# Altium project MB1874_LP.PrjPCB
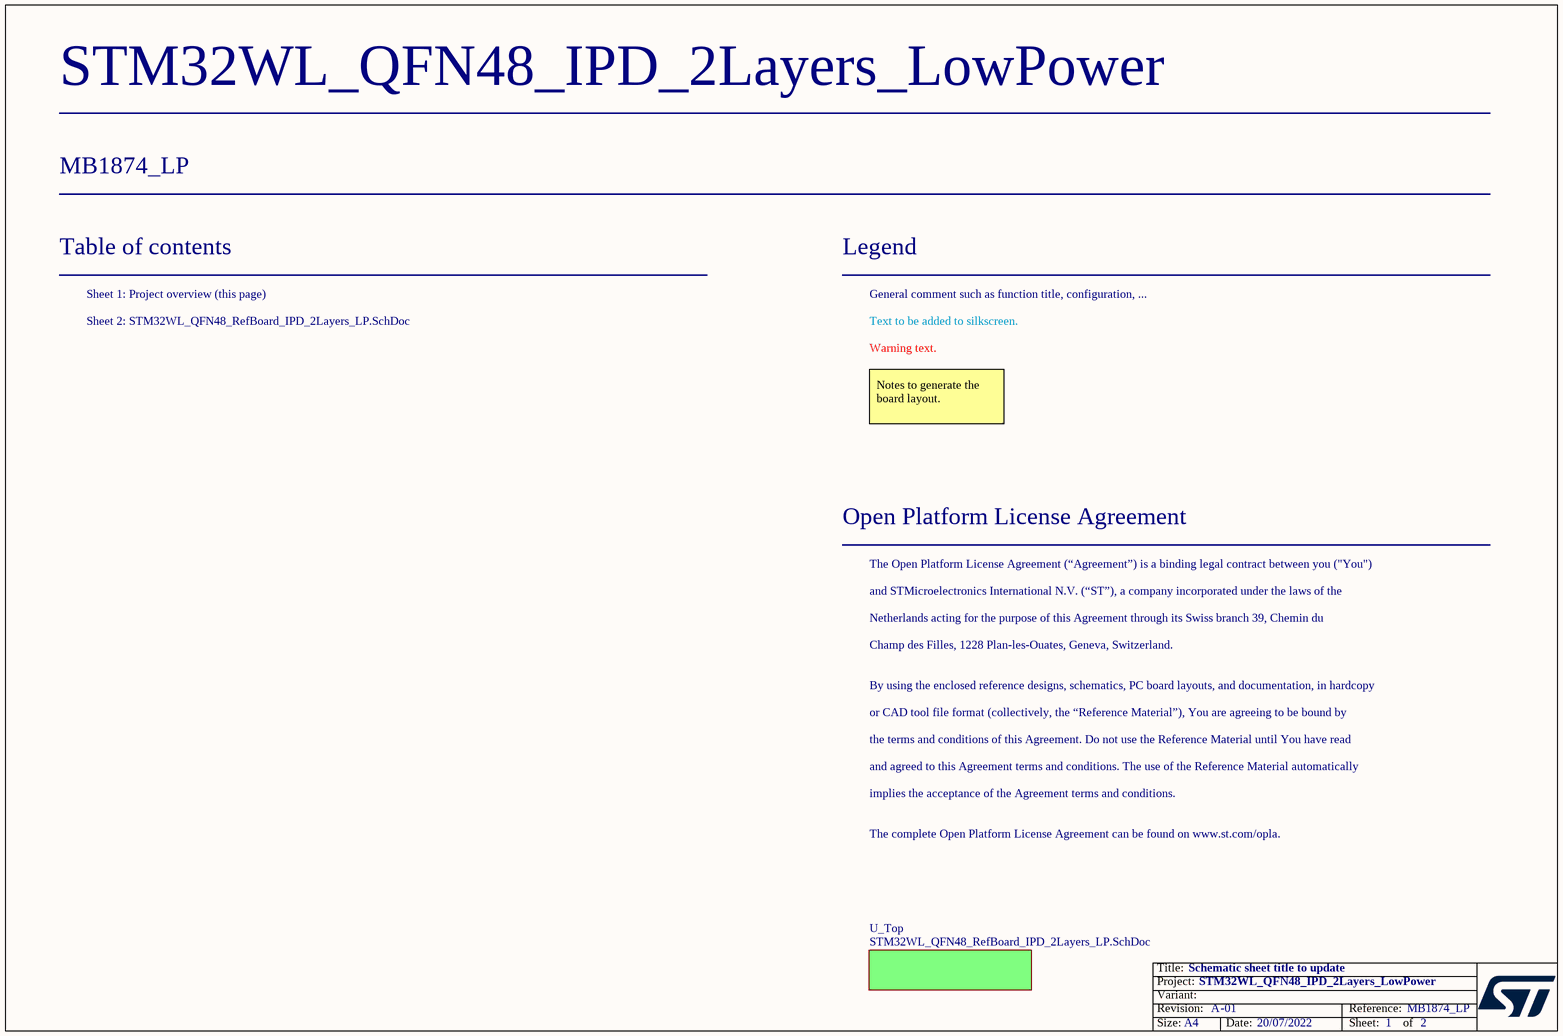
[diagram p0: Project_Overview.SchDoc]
Board_Assembly_Revision: 01; Board_Document_Date: 20/07/2022; Board_Name: STM32WL_QFN48_IPD_2Layers_LowPower; Board_PCB_Revision: A; Board_Reference: MB1874_LP
2 sheets, 73 parts. Net scope: flat (ports and power ports of the same name join across sheets).
Board file: MB1874_LP.PcbDoc
Sheets:
  Project_Overview.SchDoc
    U_Top = STM32WL_QFN48_RefBoard_IPD_2Layers_LP.SchDoc

## Sheet Project_Overview.SchDoc: Schematic sheet title to update
size A4; Date: Not used; ApprovedBy: Not used; CheckedBy: Not used; Author: Not used; CompanyName: STMicroelectronics; DrawnBy: Not used; Engineer: Not used; Organization: Not used; Address1: Not used; Address2: Not used; Address3: Not used; Address4: Not used; DocumentNumber: Not used; Revision: Not used; SheetNumber: 1; SheetTotal: 2

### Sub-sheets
U_Top = STM32WL_QFN48_RefBoard_IPD_2Layers_LP.SchDoc: no entries

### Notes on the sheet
- Table of contents
- Sheet 1: Project overview (this page)
- Legend
- General comment such as function title, configuration, ...
- Sheet 2: STM32WL_QFN48_RefBoard_IPD_2Layers_LP.SchDoc
- Text to be added to silkscreen.
- Warning text.
- Notes to generate the board layout.
- Open Platform License Agreement
- The Open Platform License Agreement (“Agreement”) is a binding legal contract between you ("You")
- and STMicroelectronics International N.V. (“ST”), a company incorporated under the laws of the
- Netherlands acting for the purpose of this Agreement through its Swiss branch 39, Chemin du
- Champ des Filles, 1228 Plan-les-Ouates, Geneva, Switzerland.
- By using the enclosed reference designs, schematics, PC board layouts, and documentation, in hardcopy
- or CAD tool file format (collectively, the “Reference Material”), You are agreeing to be bound by
- the terms and conditions of this Agreement. Do not use the Reference Material until You have read
- and agreed to this Agreement terms and conditions. The use of the Reference Material automatically
- implies the acceptance of the Agreement terms and conditions.
- The complete Open Platform License Agreement can be found on www.st.com/opla.

## Sheet STM32WL_QFN48_RefBoard_IPD_2Layers_LP.SchDoc: STM32WL UFQFPN48 REF BOARD - Direct Tie - HP- 2L
size A3; DocumentNumber: MBxxxx; Revision: A; SheetNumber: 2; SheetTotal: 2
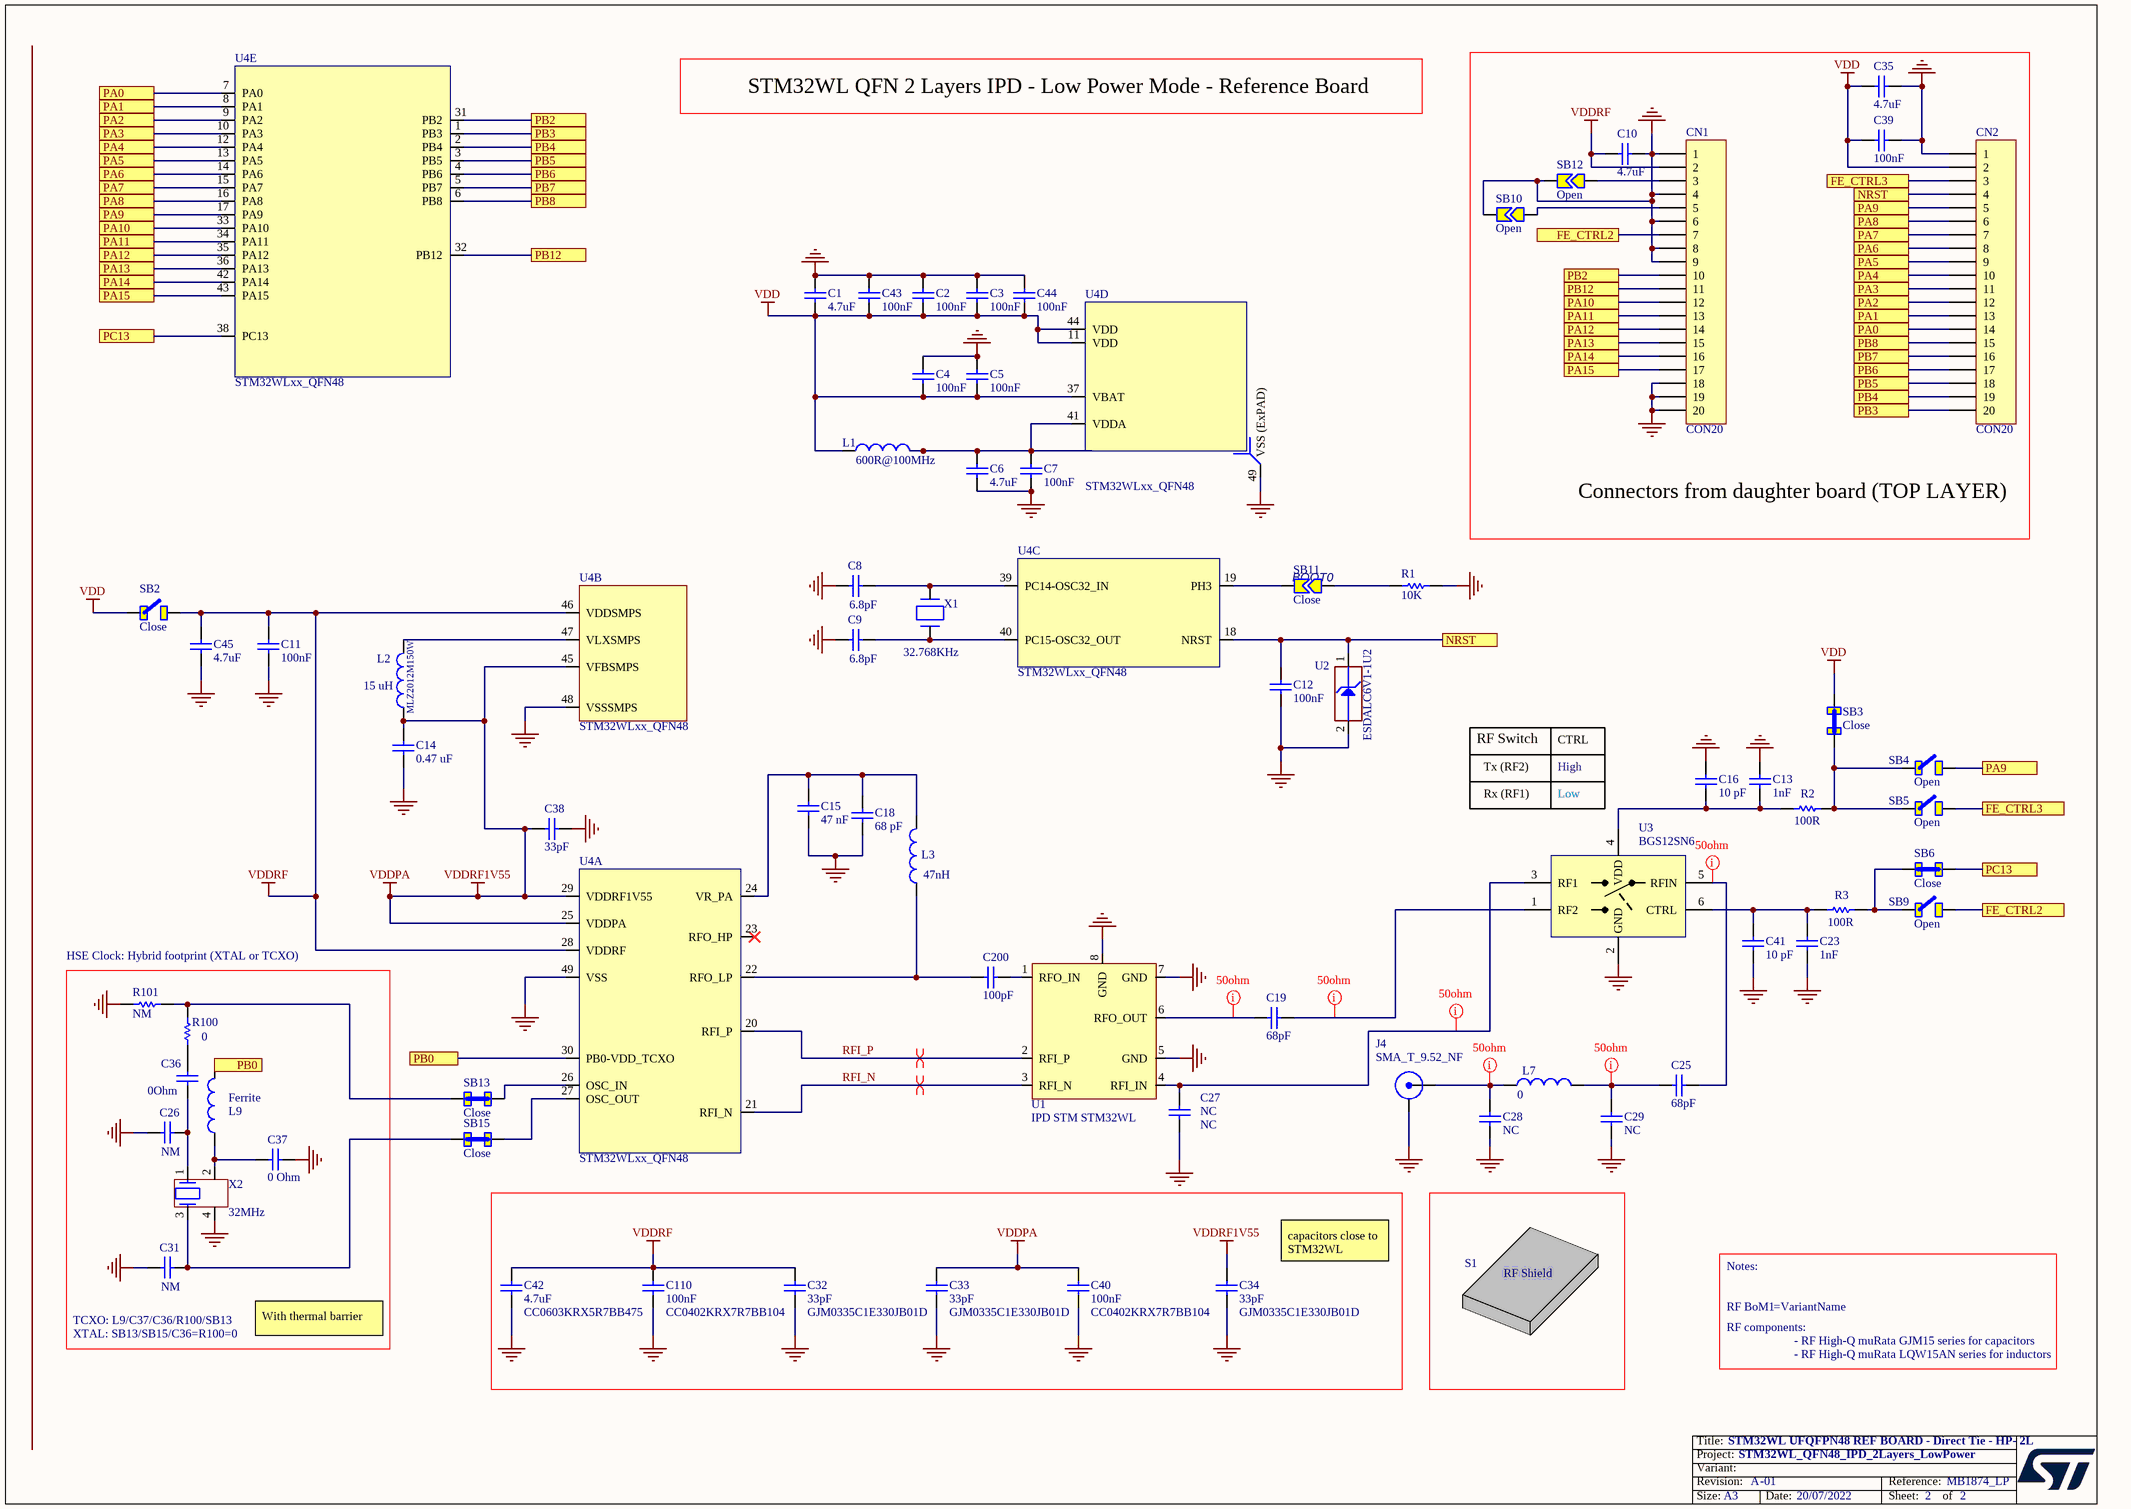
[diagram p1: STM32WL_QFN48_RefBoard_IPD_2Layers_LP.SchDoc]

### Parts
C1  value 4.7uF  [CAPC1608X09N]
C2  value 100nF  [CAPC1005X06N]
C3  value 100nF  [0201]
C4  value 100nF  [CAPC1005X06N]
C5  value 100nF  [0201]
C6  value 4.7uF  [CAPC1608X09N]
C7  value 100nF  [CAPC1005X06N]
C8  value 6.8pF  [0402]  (hidden comment: Capacitor)
C9  value 6.8pF  [0402]  (hidden comment: Capacitor)
C10  value 4.7uF  [CAPC1608X09N]
C11  value 100nF  [CAPC1005X06N]
C12  value 100nF  [0402]
C13  value 1nF  [CAPC1005X06N]
C14  value 0.47 uF  [CAPC1608X09N]
C15  value 47 nF  [0402]
C16  value 10 pF  [CAPC1005X06N]
C18  value 68 pF  [0402]
C19  value 68pF  [0402]
C23  value 1nF  [CAPC1005X06N]
C25  value 68pF  [0402_2]
C26  value NM  [0402]  (hidden comment: Capacitor)
C27  NC  [0402_2]
C28  value NC  [0402]  (hidden comment: MCD-00102)
C29  value NC  [0402]  (hidden comment: MCD-00102)
C31  value NM  [0402]  (hidden comment: Capacitor)
C32  value 33pF  Manufacturer_Part_Number: GJM0335C1E330JB01D  [0201]
C33  value 33pF  Manufacturer_Part_Number: GJM0335C1E330JB01D  [0201]
C34  value 33pF  Manufacturer_Part_Number: GJM0335C1E330JB01D  [0201]
C35  value 4.7uF  [CAPC1608X09N]
C36  value 0Ohm  [0402]
C37  value 0 Ohm  [0402]
C38  value 33pF  [0201]
C39  value 100nF  [CAPC1005X06N]
C40  value 100nF  Manufacturer_Part_Number: CC0402KRX7R7BB104  [CAPC1005X06N]
C41  value 10 pF  [CAPC1005X06N]
C42  value 4.7uF  Manufacturer_Part_Number: CC0603KRX5R7BB475  [CAPC1608X09N]
C43  value 100nF  [CAPC1005X06N]
C44  value 100nF  [0201]
C45  value 4.7uF  [CAPC1608X09N]
C110  value 100nF  Manufacturer_Part_Number: CC0402KRX7R7BB104  [CAPC1005X06N]
C200  value 100pF  [0201]  (hidden comment: MCD-00198)
CN1  CON20  [CO_SAMTEC_TSW-120-07-x-S]
CN2  CON20  [CO_SAMTEC_TSW-120-07-x-S]
J4  SMA_T_9.52_NF  [SMA_AMPHENOL_50ohms_Edge_PCB]
L1  value 600R@100MHz  [INDC1608X95N]
L2  value 15 uH  Manufacturer_Part_Number: MLZ2012M150W  [INDC2012X13N]
L3  value 47nH  [0402_COIL]
L7  value 0  [0402_COIL]
L9  Ferrite  [IND_MURATA_LQW15A]
R1  value 10K  [RESC1608X05N]
R2  value 100R  [RESC1005X04N]
R3  value 100R  [RESC1005X04N]
R100  value 0  [R0402]  (hidden comment: Resistor)
R101  value NM  [R0402]  (hidden comment: Resistor)
RF_BoM1  RF-BOM  (value not drawn)  (mechanical)
S1  RF-Shield  (value not drawn)  (mechanical)
SB2  Close  [SB_0402]
SB3  Close  [SB_0402]
SB4  Open  [SB_0402]
SB5  Open  [SB_0402]
SB6  Close  [SB_0402]
SB9  Open  [SB_0402]
SB10  Open  [GC_0402]
SB11  Close  [GC_0402]
SB12  Open  [GC_0402]
SB13  Close  [SB_0402]
SB15  Close  [SB_0402]
U1  IPD STM STM32WL  [IPD STM]
U2  Manufacturer_Part_Number: ESDALC6V1-1U2  [DIOM0603X03N]
U3  BGS12SN6  [SON40P70X40-6N]
U4  STM32WLxx_QFN48  [STM32WLxx_QFN48]  (parts A,B,C,D,E of 5)
X1  value 32.768KHz  [OSC_NDK_NX2012SA]  (hidden comment: XTAL_2_PINS)
X2  value 32MHz  [OSC_NDK_NX2016SA]

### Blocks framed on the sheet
Connectors from daughter board (TOP LAYER): C10 C35 C39 CN1 CN2 SB10 SB12

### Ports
FE_CTRL2, FE_CTRL3, NRST, PA0, PA1, PA2, PA3, PA4, PA5, PA6, PA7, PA8, PA9, PA10, PA11, PA12, PA13, PA14, PA15, PB0, PB2, PB3, PB4, PB5, PB6, PB7, PB8, PB12, PC13

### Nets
GND: C1.1 C2.1 C3.1 C4.1 C5.1 C6.2 C7.2 C8.2 C9.2 C10.2 C11.2 C12.2 C13.1 C14.2 C15.2 C16.1 C18.1 C23.1 C26.2 C27.1 C28.2 C29.2 C31.2 C32.1 C33.1 C34.1 C35.1 C37.1 C38.2 C39.2 C40.2 C41.2 C42.2 C43.1 C44.1 C45.2 C110.2 CN1.1 CN1.4 CN1.6 CN1.8 CN1.9 CN1.18 CN1.19 CN1.20 CN2.1 J4.2(Y) R1.1 R101.2 SB10.2 SB12.2 U1.5(GND) U1.7(GND) U1.8(GND) U2.2(GND) U3.2(GND) U4.48(VSSSMPS) U4.49(VSS_(ExPAD)) X2.4
VDD: C1.2 C2.2 C3.2 C4.2 C5.2 C35.2 C39.1 C43.2 C44.2 CN2.2 L1.1 SB2.2 SB3.1 U4.11(VDD) U4.37(VBAT) U4.44(VDD)
VDDPA: C14.1 C33.2 C34.2 C38.1 C40.1 L2.1 U4.25(VDDPA) U4.29(VDDRF1V55) U4.45(VFBSMPS)  [also labelled VDDRF1V55]
VDDRF: C10.1 C11.1 C32.2 C42.1 C45.1 C110.1 CN1.2 SB2.1 U4.28(VDDRF) U4.46(VDDSMPS)
FE_CTRL2: CN1.7 SB9.1 ; port FE_CTRL2
FE_CTRL3: CN2.3 SB5.1 ; port FE_CTRL3
NRST: C12.1 CN2.4 U2.1(IO1) U4.18(NRST) ; port NRST
PA0: CN2.14 U4.7(PA0) ; port PA0
PA1: CN2.13 U4.8(PA1) ; port PA1
PA2: CN2.12 U4.9(PA2) ; port PA2
PA3: CN2.11 U4.10(PA3) ; port PA3
PA4: CN2.10 U4.12(PA4) ; port PA4
PA5: CN2.9 U4.13(PA5) ; port PA5
PA6: CN2.8 U4.14(PA6) ; port PA6
PA7: CN2.7 U4.15(PA7) ; port PA7
PA8: CN2.6 U4.16(PA8) ; port PA8
PA9: CN2.5 SB4.1 U4.17(PA9) ; port PA9
PA10: CN1.12 U4.33(PA10) ; port PA10
PA11: CN1.13 U4.34(PA11) ; port PA11
PA12: CN1.14 U4.35(PA12) ; port PA12
PA13: CN1.15 U4.36(PA13) ; port PA13
PA14: CN1.16 U4.42(PA14) ; port PA14
PA15: CN1.17 U4.43(PA15) ; port PA15
PB0: L9.2 U4.30(PB0-VDD_TCXO) ; port PB0
PB2: CN1.10 U4.31(PB2) ; port PB2
PB3: CN2.20 U4.1(PB3) ; port PB3
PB4: CN2.19 U4.2(PB4) ; port PB4
PB5: CN2.18 U4.3(PB5) ; port PB5
PB6: CN2.17 U4.4(PB6) ; port PB6
PB7: CN2.16 U4.5(PB7) ; port PB7
PB8: CN2.15 U4.6(PB8) ; port PB8
PB12: CN1.11 U4.32(PB12) ; port PB12
PC13: SB6.1 U4.38(PC13) ; port PC13
RFI_N: U1.3(RFI_N) U4.21(RFI_N)
RFI_P: U1.2(RFI_P) U4.20(RFI_P)
NetC6_1: C6.1 C7.1 L1.2 U4.41(VDDA)
NetC8_1: C8.1 U4.39(PC14-OSC32_IN) X1.2(X2)
NetC9_1: C9.1 U4.40(PC15-OSC32_OUT) X1.1(X1)
NetC13_2: C13.2 C16.2 R2.1 U3.4(VDD)
NetC15_1: C15.1 C18.2 L3.1 U4.24(VR_PA)
NetC19_1: C19.1 U3.1(RF2)
NetC19_2: C19.2 U1.6(RFO_OUT)
NetC23_2: C23.2 C41.1 R3.1 U3.6(CTRL)
NetC25_1: C25.1 U3.5(RFIN)
NetC25_2: C25.2 C29.1 L7.1
NetC26_1: C26.1 C36.2 X2.1
NetC27_2: C27.2 U1.4(RFI_IN) U3.3(RF1)
NetC28_1: C28.1 J4.1(X) L7.2
NetC31_1: C31.1 SB15.2 X2.3
NetC36_1: C36.1 R100.2
NetC37_2: C37.2 L9.1 X2.2
NetC200_1: C200.1 U1.1(RFO_IN)
NetC200_2: C200.2 L3.2 U4.22(RFO_LP)
NetCN1_3: CN1.3 SB12.1
NetCN1_5: CN1.5 SB10.1
NetL2_2: L2.2 U4.47(VLXSMPS)
NetR1_2: R1.2 SB11.1
NetR2_2: R2.2 SB3.2 SB4.2 SB5.2
NetR3_2: R3.2 SB6.2 SB9.2
NetR100_1: R100.1 R101.1 SB13.2
NetSB11_2: SB11.2 U4.19(PH3)
NetSB13_1: SB13.1 U4.26(OSC_IN)
NetSB15_1: SB15.1 U4.27(OSC_OUT)

Not connected (* = marked no-connect by the designer): U4 23(RFO_HP)*

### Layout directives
net class 50ohm: NetC19_1, NetC19_2, NetC25_1, NetC25_2, NetC27_2, NetC28_1
differential pair: RFI_N, RFI_P

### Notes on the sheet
- STM32WL QFN 2 Layers IPD - Low Power Mode - Reference Board
- (near SB11) BOOT0
- RF Switch
- Tx (RF2)
- CTRL
- High
- Rx (RF1)
- Low
- HSE Clock: Hybrid footprint (XTAL or TCXO)
- capacitors close to STM32WL
- (near C31) TCXO: L9/C37/C36/R100/SB13
- Notes:
- XTAL: SB13/SB15/C36=R100=0
- With thermal barrier
- RF components:
- (near RF_BoM1) - RF High-Q muRata GJM15 series for capacitors
- (near RF_BoM1) - RF High-Q muRata LQW15AN series for inductors

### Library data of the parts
C1 C6 C10 C35 C45 = MCD-00009: Capacitor, MLCC, 4.7uF, 16V, X5R, 10%, 0603, T=0.8mm; Manufacturer_Part_Number: CC0603KRX5R7BB475; Manufacturer: YAGEO
C2 C4 C7 C11 C12 C39 C43 = MCD-00102: Capacitor, MLCC, 100nF, 16V, X7R, 10%, 0402, T=0,5mm; Manufacturer_Part_Number: CC0402KRX7R7BB104; Manufacturer: YAGEO
C3 C5 C44 = MCD-00102: Multilayer Ceramic Capacitors MLCC - SMD/SMT 0201 25VDC 0.1uF 10% X5R 0.3mm; Manufacturer_Part_Number: C0603X5R1E104K030BB; Manufacturer: TDK
C8 C9 C26 C31 = MCD-00003: Capacitor, MLCC, 6.8pF, 50V, NPO, +-0.1pF, 0402, T=0.5mm; Manufacturer_Part_Number: GRM1555C1H6R8BA01; Manufacturer: MURATA
C13 C23 = MCD-00198: Capacitor, MLCC, 1nF, 16V, X7R, 10%, 0402, T=0.5mm; Manufacturer_Part_Number: CC0402KRX7R7BB102; Manufacturer: YAGEO
C14 = MCD-00009: Capacitor, MLCC, 0.47 uF, 16V, X5R, 10%, 0603, T=0.8mm; Manufacturer_Part_Number: CC0603KRX5R7BB474; Manufacturer: YAGEO
C15 = MCD-01123: Capacitor, MLCC,47nF, 25V, X7R, 10%, 0402, T=0.5mm; Manufacturer_Part_Number: GCM155R71E473KA55; Manufacturer: MURATA
C16 C41 = MCD-00102: Capacitor, MLCC, 10 pF; Manufacturer_Part_Number: GJM1555C1H100FB01D; Manufacturer: MURATA
C18 = MCD-01123: Capacitor, MLCC,68pF, 50V, C0G, 1%, 0402, T=0.5mm; Manufacturer_Part_Number: GCM1555C1H680JA16; Manufacturer: MURATA
C19 = MCD-01123: Condensateurs céramique multicouches MLCC - CMS 33PF 50V 2% 0402
C25 = MCD-01123: Multilayer Ceramic Capacitors MLCC - SMD/SMT 0402 68pF 50volts C0G 5%
C27 = MCD-01123: Not connected [0402]
C28 C29 = MCD-00102: Condensateurs céramique multicouches MLCC - CMS 0402 3.3pF 50Volts C0G +/-0.05pF
C32-C34 = MCD-00277: Multilayer Ceramic Capacitors MLCC - SMD/SMT 0201 33pF 25volts C0G 5%; Manufacturer: MURATA
C36 C37 = MCD-00277: Capacitor, MLCC, 33pF, 50V, NPO, 2%, 0402, T=0,5mm; Manufacturer_Part_Number: RCS04020000Z0ED; Manufacturer: Vishay / Dale
C38 = MCD-01123: Multilayer Ceramic Capacitors MLCC - SMD/SMT 0201 33pF 25volts C0G 5%; Manufacturer_Part_Number: GJM0335C1E330JB01D; Manufacturer: MURATA
C40 C110 = MCD-00102: Capacitor, MLCC, 100nF, 16V, X7R, 10%, 0402, T=0,5mm; Manufacturer: YAGEO
C42 = MCD-00009: Capacitor, MLCC, 4.7uF, 16V, X5R, 10%, 0603, T=0.8mm; Manufacturer: YAGEO
C200 = MCD-00198: Multilayer ceramic capacitors COG +/-5%, 50V; Manufacturer_Part_Number: GRM033R71H102KA12D; Manufacturer: MURATA
CN1 CN2 = CON20: Connector right-angle, pitch 2.54mm, 20 contacts; Manufacturer: SAMTEC; Manufacturer_Part_Number: TSW-120-07-L-S
J4 = SMA_T_9.52_NF: SMA Jack, Edge Mount, 50 Ohms; Manufacturer: Johnson / Cinch Connectivity Solutions; Manufacturer_Part_Number: 142-0701-881
L1 = MCD-00047: SMD Chip ferrite bead, 600R@100MHz +/-25%, 350mA, 500mohm DC, 0603, T=0.8mm; Manufacturer_Part_Number: BK1608HS601-T; Manufacturer: Taiyo Yuden
L2 = MCD-01433: MLZ2012 Multilayer Shielded Inductor 15 uH, ±5%; Manufacturer: TDK
L3 = MCD-01330: Inductor, 68nH, +-0.1nH, 140mA, 0402
L7 = MCD-01330: Inductor, 15nH, +-0.1nH, 640mA, 0402
L9 = MCD-01330: Inductor, 3.9nH, +-0.1nH, 750mA, 0402; Manufacturer: MURATA; Value: LQW15AN3N9B00#; Provided_By: SUBCO; Initial_Board_Reference: MB1402
R1 = MCD-00220: Resistor,10K,0603,1%,1/10W; Manufacturer_Part_Number: RC0603FR-0710KL; Manufacturer: YAGEO
R2 R3 = MCD-00119: Resistor,100R,0402,1%,1/16W; Manufacturer_Part_Number: RC0402FR-07100RL; Manufacturer: YAGEO
R100 R101 = MCD-00052: Resistor,0R,0402,5%,1/16W; Manufacturer_Part_Number: RC0402JR-070RL; Manufacturer: YAGEO; Provided_By: SUBCO; Initial_Board_Reference: MB1274
S1 = RF-Shield: RF Shield Frame + Cover without apertures; Manufacturer: Masach Tech; Manufacturer_Part_Number: MS409-10
SB2 SB4 SB5 SB9 = SB_Open: Solder Bridge Open [0402] (Unpopulated)
SB3 SB6 = SB_0Ohm: Solder Bridge 0R [0402] (Populated with 0 Ohm); Manufacturer: Vishay / Dale; Manufacturer_Part_Number: RCS04020000Z0ED; VALUE: 0 ohm
SB10 SB12 = Strap2: Solder Jumper - Open; Manufacturer: Vishay / Dale; Manufacturer_Part_Number: RCS04020000Z0ED
SB11 = Strap2: Solder Jumper - Close; Manufacturer: Vishay / Dale; Manufacturer_Part_Number: RCS04020000Z0ED
SB13 SB15 = SB_0Ohm: Solder Bridge 0R [0402] (Populated with 0 Ohm); Manufacturer: Vishay / Dale; Manufacturer_Part_Number: RCS04020000Z0ED; VALUE: 0
U1 = IPD ST STM32WL: Manufacturer: STMICROELECTRONICS
U2 = MCD-00170: ESD protection 6V1; Manufacturer: STMICROELECTRONICS
U3 = BGS12SN6: DC switch - Ultra-Low  SPDT analog switch; Manufacturer: INFINEON
U4 = STM32WLxx_QFN48: STM32WL ARM MCU Multiprotocol LPWAN 32-bit Arm Cortex-M4 MCUs LoRa (G)FSK-MSK BPSK; Manufacturer_Part_Number: STM32WLE5CC; Manufacturer: STMicroelectronics
X1 = MCD-01479: Crystal 32.768kHz, 6pF, -+20PPM, R=80K, SMD; Manufacturer_Part_Number: NX2012SA 32.768KHz EXS00A-MU00527; Manufacturer: NDK
X2 = MCD-01446: Crystal 32 MHz, 8pF, -+10 PPM, R=60Ω, SMD; Manufacturer_Part_Number: NX2016SA 32MHz EXS00A-CS06465; Manufacturer: NDK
